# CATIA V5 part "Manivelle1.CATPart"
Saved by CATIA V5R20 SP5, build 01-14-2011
Part number: Manivelle1
Publications: "Longueur_Manivelle1"
Bounding box of the stored display mesh (mm): x -30 to 10, y -80 to 80, z -20 to 20
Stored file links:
  F:\IAO\Projet_IAO5.0\Manivelle1.CATPart
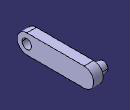
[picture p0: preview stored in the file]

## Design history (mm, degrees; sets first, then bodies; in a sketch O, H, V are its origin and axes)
Parameters
  Longueur_Manivelle1 = 120 mm
Body1 (main body)
  Sketch1 on yz-plane, origin (0, 0, 0), H (0, 1, 0), V (0, 0, 1)
    circle A1 centre (-60, 0) radius 10
    point P1 (-60, 0)
    circle A2 centre (-60, 0) radius 15
    circle A3 centre (60, 0) radius 10
    point P2 (60, 0)
    circle A4 centre (60, 0) radius 15
    radius A1 = 10
    radius A2 = 15
    radius A3 = 10
    radius A4 = 15
    distance P1 P2 = 120 {= Longueur_Manivelle1}
    distance P2 V = 60 {= Longueur_Manivelle1 /2}
    coincidence: P1 H, P2 H
  Pad1: profile Sketch1, direction (1, 0, 0), length 10, mirrored extent
  Sketch2 on zx-plane, origin (0, 0, 0), H (-1, 0, 0), V (0, 0, 1)
    circle A1 centre (0, 0) radius 10
    radius A1 = 10
  Pad2: profile Sketch2, direction (0, 1, 0), up to face of Pad1 from Sketch1.A4, opposite side up to face of Pad1 from Sketch1.A2
  Sketch3 on end face of Pad1, origin (10, 0, 0), H (0, 1, 0), V (0, 0, 1)
    circle A1 centre (60, 0) radius 10
    point P1 (60, 0)
    radius A1 = 10
    distance O P1 = 60 {= Longueur_Manivelle1/2}
    coincidence: H P1
  Pad3: profile Sketch3, direction (-1, 0, 0), length 40
  Sketch4 on yz-plane, origin (0, 0, 0), H (0, 1, 0), V (0, 0, 1)
    construction line L1 (-60, 0) -> (60, 0)
    point P1 (-60, 0)
    point P2 (60, 0)
    line L2 (-60, 20) -> (60, 20)
    line L3 (60, -20) -> (-60, -20)
    arc A1 centre (60, 0) radius 20 from (60, 20) to (60, -20) cw
    arc A2 centre (-60, 0) radius 20 from (-60, -20) to (-60, 20) cw
    circle A3 centre (-60, 0) radius 10
    distance L1 L2 = 20
    distance P1 P2 = 120 {= Longueur_Manivelle1}
    distance V P2 = 60 {= Longueur_Manivelle1 /2}
    radius A3 = 10
    horizontal: L1 H
    tangency: A1 L2, A2 L2, A1 L3, A2 L3
    coincidence: L1 H
  Pad4: profile Sketch4, direction (-1, 0, 0), length 10, mirrored extent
